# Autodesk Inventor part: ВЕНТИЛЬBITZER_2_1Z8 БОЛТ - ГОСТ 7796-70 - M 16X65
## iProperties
Created: 2011-02
Part Number: ВЕНТИЛЬBITZER_2_1Z8 БОЛТ - ГОСТ 7796-70 - M 16X65
Document SubType Name: Modeling
Designer: Чернышев Юрий
Mass: 16.7089 g
Surface Area: 47.6443 cm^2
Volume: 16.7089 cm^3
Density: 1 g/cm^3
Author: Чернышев Юрий
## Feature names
1. Base1
